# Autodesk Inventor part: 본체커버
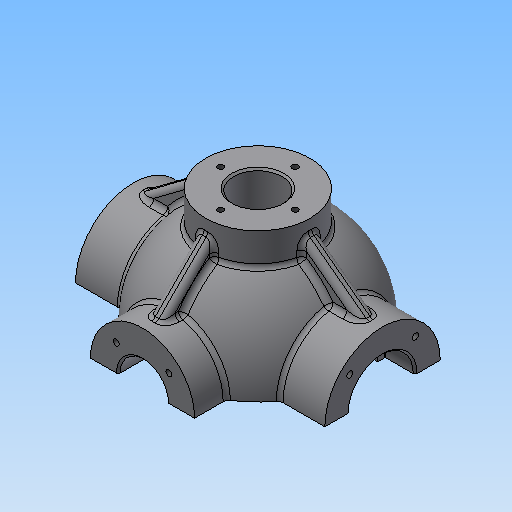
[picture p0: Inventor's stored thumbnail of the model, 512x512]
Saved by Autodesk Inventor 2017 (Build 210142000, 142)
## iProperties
Created: 2015-12
Part Number: 본체커버
Material: 일반
Document SubType Name: Modeling
Designer: mduedu
Density: 1 g/cm^3
Mass: 217.614 g
Surface Area: 460.056 cm^2
Volume: 217.614 cm^3
Appearance: 기본값
Author: mduedu
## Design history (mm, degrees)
sketch "스케치1"
  geometry: L1 (-53, 0)-(53, 0); A1 r 53 centre (0, 0) between (53, 0) and (-53, 0); 2 further points
  constraints: 2 coincident, 2 end point, 2 point on circle, 1 centre point, 1 horizontal, 1 midpoint
  dimensions: "d0" = 53 radius of A1
revolve "회전1" sketch "스케치1" stored, may be unused: angle "d2" = 90 deg
feature "쉘1" dims "d11" = 10
node "작업 평면1"
sketch "스케치2"
  geometry: C1 r 31 at (0, 0); 1 further point
  constraints: 1 centre point, 1 coincident
  dimensions: "d4" = 62 diameter of C1
extrude "돌출1" join sketch "스케치2" stored distance "d5" = 10; taper "d6" = 0 deg
node "작업 평면2"
sketch "스케치3"
  geometry: C1 r 28 at (0, 0); 1 further point
  constraints: 1 centre point, 1 coincident
  dimensions: "d8" = 56 diameter of C1
extrude "돌출2" join sketch "스케치3" stored distance "d9" = 10; taper "d10" = 0 deg
hole "구멍1" diameter "d14" = 35; stored, may be unused: countersink angle "d18" = 90 deg, drill point angle "d20" = 0 deg; dims "d12" = 10, "d13" = 10, "d15" = 6, "d16" = 4, "d17" = 2, "d19" = 16
hole "구멍2" diameter "d23" = 27; stored, may be unused: countersink angle "d27" = 90 deg, drill point angle "d29" = 0 deg; dims "d21" = 10, "d22" = 10, "d24" = 6, "d25" = 4, "d26" = 2, "d28" = 16
fillet "모깎기1" dims "d30" = 0.3
hole "구멍3" diameter "d33" = 26; stored, may be unused: countersink angle "d37" = 90 deg, drill point angle "d39" = 0 deg; dims "d31" = 10, "d32" = 10, "d34" = 6, "d35" = 4, "d36" = 2, "d38" = 16
chamfer "모따기1" distance "d40" = 1; stored, may be unused: second distance "d41" = 2, angle "d42" = 45 deg
sketch "스케치4"
  geometry: L1 (0, 0)-(0, -25); L2 (0, 0)-(-17.678, -17.678); A1 r 25 centre (0, 0) between (-17.678, -17.678) and (0, -25); 1 further point
  constraints: 4 end point, 2 point on circle, 1 centre point, 1 coincident, 1 vertical
  dimensions: "d43" = 50 diameter of A1; "d47" = 45 deg angle of L1 L2
hole "구멍4" sketch "스케치4" at (-17.678, -17.678) diameter "d49" = 3.242; stored, may be unused: countersink angle "d53" = 90 deg, drill point angle "d55" = 118 deg; dims "d50" = 11, "d51" = 4, "d52" = 2, "d54" = 13
sketch "스케치5"
  geometry: L1 (0, 0)-(0, -20); L2 (0, 0)-(-14.142, -14.142); A1 r 20 centre (0, 0) between (0, -20) and (-14.142, -14.142); 2 further points
  constraints: 4 end point, 2 coincident, 2 point on circle, 1 centre point, 1 vertical
  dimensions: "d59" = 40 diameter of A1; "d65" = 45 deg angle of L1 L2
hole "구멍5" sketch "스케치5" at (-14.142, -14.142) diameter "d67" = 3.242; stored, may be unused: countersink angle "d71" = 90 deg, drill point angle "d73" = 118 deg; dims "d68" = 8, "d69" = 4, "d70" = 2, "d72" = 10
node "작업 평면3"
sketch "스케치6"
  geometry: C1 r 65 at (0, 0); 1 further point
  constraints: 1 centre point, 1 coincident
  dimensions: "d78" = 130 diameter of C1
extrude "돌출3" join sketch "스케치6" distance "d80" = 10; taper "d81" = 0 deg
sketch "스케치7"
  geometry: C1 r 20 at (0, 0); 1 further point
  constraints: 1 centre point, 1 coincident
  dimensions: "d82" = 40 diameter of C1
extrude "돌출4" join sketch "스케치7" stored distance "d84" = 10; taper "d85" = 0 deg
sketch "스케치8"
  geometry: 2 further points
  constraints: 1 coincident
hole "구멍6" sketch "스케치8" at (0, 0) diameter "d86" = 20; stored, may be unused: countersink angle "d90" = 90 deg, drill point angle "d92" = 118 deg; dims "d87" = 7, "d88" = 40, "d89" = 5, "d91" = 10
fillet "모깎기2" dims "d93" = 0.3
sketch "스케치9"
  geometry: L1 (65, -75)-(-65, -75) reference; L2 (-45, -75)-(-38.245, -36.692); A1 r 53 centre (0, 0) between (42.988, 31) and (42.988, -31) reference; 1 further point
  constraints: 2 end point, 1 point on circle, 1 point on line
  dimensions: "d94" = 45 horizontal distance of L2.start point (0, 0); "d95" = 80 deg angle of L2 L1
feature "리브1" sketch "스케치9" dims "d96" = 1, "d97" = 8, "d98" = 0, "d99" = 0, "d100" = 1, "d101" = 1
sketch "스케치10"
  geometry: L1 (0, 0)-(0, -55); L2 (0, 0)-(-38.891, -38.891); A1 r 55 centre (0, 0) between (0, -55) and (-38.891, -38.891); 2 further points
  constraints: 4 end point, 2 coincident, 2 point on circle, 1 centre point, 1 vertical
  dimensions: "d105" = 110 diameter of A1; "d107" = 45 deg angle of L1 L2
hole "구멍7" sketch "스케치10" at (-38.891, -38.891) diameter "d109" = 10; stored, may be unused: countersink angle "d113" = 90 deg, drill point angle "d115" = 118 deg; dims "d110" = 7, "d111" = 40, "d112" = 5, "d114" = 10
fillet "모깎기3" dims "d120" = 3
fillet "모깎기4" dims "d121" = 3, "d122" = 3
fillet "모깎기5" dims "d123" = 3
fillet "모깎기6" dims "d124" = 3
sketch "스케치11"
  geometry: C1 r 5 at (-38.891, 38.891) reference; C2 r 5 at (38.891, 38.891) reference; C3 r 5 at (38.891, -38.891) reference; C4 r 5 at (-38.891, -38.891) reference; C5 r 20 at (0, 0) reference; C6 r 65 at (0, 0) reference; 1 further point
  constraints: 3 other
feature "엠보싱1" sketch "스케치11" dims "d125" = 0.5, "d126" = 0
sketch "스케치12"
  geometry: L1 (0, 100)-(0, -100); L2 (0, 100)-(-150, 100); L3 (-150, 100)-(-150, -100); L4 (-150, -100)-(0, -100); 2 further points
  constraints: 8 end point, 3 perpendicular, 1 coincident, 1 midpoint, 1 vertical
  dimensions: "d127" = 200 distance of L2.end L3.end; "d129" = 150 distance of L3.end L1.end
extrude "돌출5" cut sketch "스케치12" stored distance "d130" = 10; taper "d131" = 0 deg
sketch "스케치13"
  geometry: C1 r 7 at (0, -53); A1 r 53 centre (0, 0) between (-42.113, -32.179) and (42.113, -32.179) reference; 1 further point
  constraints: 1 centre point, 1 point on circle
  dimensions: "d132" = 14 diameter of C1
extrude "돌출6" join sketch "스케치13" distance "d133" = 5; taper "d134" = 0 deg
sketch "스케치14"
  geometry: C1 r 7 at (0, 0) reference; 1 further point
extrude "돌출7" cut sketch "스케치14" stored distance "d135" = 5; taper "d136" = 0 deg
sketch "스케치15"
  geometry: C1 r 2.25 at (0, 53); A1 r 7 centre (0, 53) between (6.965, 52.302) and (-6.965, 52.302) reference; 1 further point
  constraints: 1 centre point, 1 coincident
  dimensions: "d139" = 4.5 diameter of C1
extrude "돌출8" cut sketch "스케치15" stored distance "d141" = 5; taper "d142" = 0 deg
fillet "모깎기7" dims "d143" = 3
fillet "모깎기8" dims "d144" = 1
fillet "모깎기9" dims "d145" = 1
fillet "모깎기10" dims "d146" = 1
node "작업 평면4"
sketch "스케치16"
  geometry: C1 r 28 at (0, 0); 1 further point
  constraints: 1 centre point, 1 coincident
  dimensions: "d148" = 56 diameter of C1
extrude "돌출9" join sketch "스케치16" stored distance "d150" = 5; taper "d151" = 0 deg
hole "구멍8" diameter "d154" = 26; stored, may be unused: countersink angle "d158" = 90 deg, drill point angle "d160" = 118 deg; dims "d152" = 10, "d153" = 10, "d155" = 6, "d156" = 4, "d157" = 2, "d159" = 8
sketch "스케치17" dims "d161" = 40
  geometry: 3 further points
  constraints: 2 vertical alignment, 1 coincident, 2 other
hole "구멍9" sketch "스케치17" at (0, 20) diameter "d163" = 3.242; stored, may be unused: countersink angle "d167" = 90 deg, drill point angle "d169" = 118 deg; dims "d164" = 8, "d165" = 4, "d166" = 2, "d168" = 10
fillet "모깎기11" dims "d173" = 3
chamfer "모따기2" distance "d174" = 1; stored, may be unused: second distance "d175" = 2, angle "d176" = 45 deg
sketch "스케치18"
  geometry: L1 (28, 62)-(28, 46.637) reference; L2 (67, 31)-(44.497, 31) reference; L3 (28, 55)-(60, 31); L4 (-28, 62)-(28, 62) reference; L5 (67, 31)-(67, 0) reference; 1 further point
  constraints: 2 end point, 2 point on line
  dimensions: "d177" = 7 distance from line of L3.start L4; "d178" = 7 distance from line of L3.end L5
feature "리브2" sketch "스케치18" dims "d179" = 1, "d180" = 8, "d181" = 0, "d182" = 0, "d183" = 1, "d184" = 1
fillet "모깎기12" dims "d185" = 3
fillet "모깎기13" dims "d186" = 3
sketch "스케치19"
  geometry: L1 (62, 28)-(46.637, 28) reference; L2 (28, 62)-(28, 46.637) reference; L3 (55, 28)-(28, 55); L4 (0, 62)-(28, 62) reference; L5 (62, 28)-(62, -28) reference; 1 further point
  constraints: 2 end point, 2 point on line
  dimensions: "d187" = 7 distance from line of L3.end L4; "d188" = 7 distance from line of L3.start L5
feature "리브3" sketch "스케치19" dims "d189" = 1, "d190" = 8, "d191" = 0, "d192" = 0, "d193" = 1, "d194" = 1
fillet "모깎기14" dims "d195" = 3
fillet "모깎기15" dims "d196" = 3
node "솔리드1"
mirror "대칭1"
mirror "대칭2"
pattern_circular "원형 패턴1" dims angle "d57" = 360 deg
mirror "대칭3"
pattern_circular "원형 패턴2" dims angle "d75" = 360 deg
pattern_circular "원형 패턴3" dims angle "d103" = 360 deg
pattern_circular "원형 패턴4" dims angle "d118" = 360 deg
pattern_circular "원형 패턴5" dims angle "d171" = 360 deg
mirror "대칭4"
node "투영된 루프1"
other parameters: "d3" = 67, "d7" = 62, "d77" = -85, "d147" = 62
